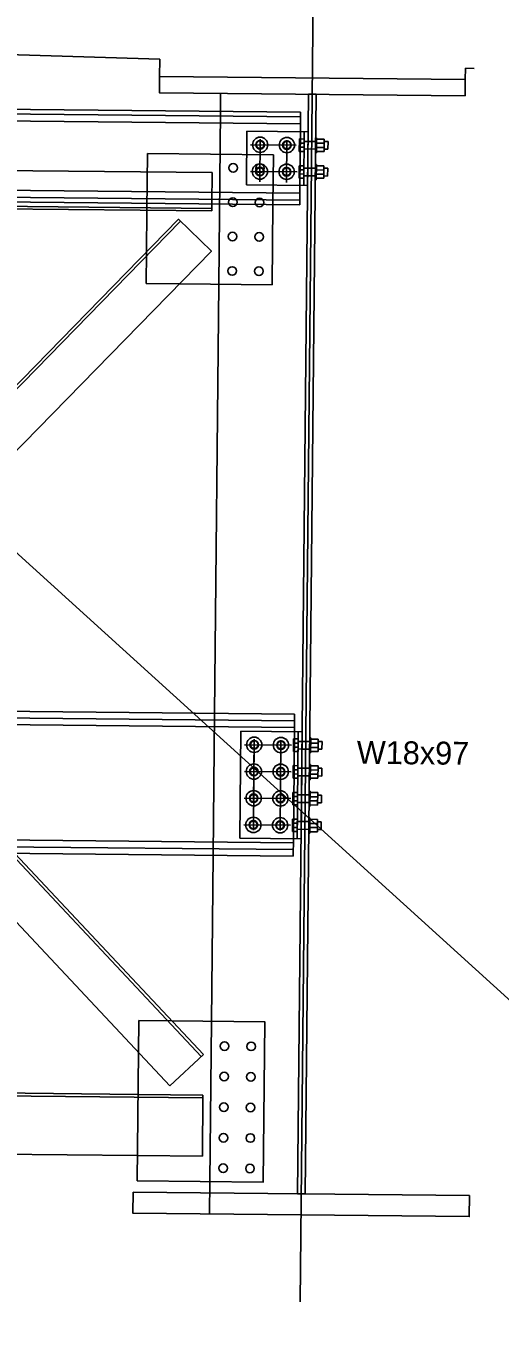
# Model space of a CAD drawing. Extents: x 632312 to 632885, y 378199 to 378534.
# Drawn here: x 632775.42 to 632780.59, y 378341.77 to 378355.92 of the extents above; entities that cross this region are included whole.
import ezdxf

# ---------------------------------------------------------------- set-up
doc = ezdxf.new("R2010")
doc.units = 0
for name, color, linetype in [('B_Boring', 7, 'Continuous'), ('B_Boring Annot', 7, 'Continuous'), ('R_Proposed Const Limits Cut', 7, 'Continuous'), ('R_Shade Removal', 7, 'Continuous'), ('R_Wall', 7, 'Continuous'), ('SHT_Dimensions', 7, 'Continuous'), ('USACE_Easement', 7, 'Continuous')]:
    doc.layers.add(name, color=color, linetype=linetype)

msp = doc.modelspace()

# ---------------------------------------------------------------- linework, layer by layer
at = {"layer": 'B_Boring'}
for p, q in [((632777.54, 378354.984), (632777.542, 378355.183)), ((632778.415, 378354.925), (632767.415, 378355.034)), ((632778.415, 378354.975), (632767.416, 378355.084)), ((632778.413, 378354.763), (632778.415, 378354.975)), ((632777.83, 378354.768), (632777.824, 378354.185)), ((632778.497, 378354.762), (632777.83, 378354.768)), ((632778.402, 378354.685), (632778.401, 378354.549)), ((632778.454, 378354.684), (632778.402, 378354.685)), ((632778.449, 378354.179), (632778.455, 378354.762)), ((632778.454, 378354.684), (632778.453, 378354.549)), ((632778.491, 378354.178), (632778.497, 378354.762)), ((632778.579, 378354.698), (632778.578, 378354.532)), ((632778.579, 378354.698), (632778.59, 378354.698)), ((632778.59, 378354.698), (632778.588, 378354.532)), ((632778.589, 378354.683), (632778.673, 378354.682)), ((632778.673, 378354.682), (632778.671, 378354.546)), ((632778.453, 378354.594), (632778.401, 378354.594)), ((632778.453, 378354.549), (632778.401, 378354.549)), ((632778.454, 378354.639), (632778.402, 378354.639)), ((632778.588, 378354.547), (632778.671, 378354.546)), ((632778.589, 378354.638), (632778.672, 378354.637)), ((632778.589, 378354.592), (632778.672, 378354.592)), ((632778.672, 378354.572), (632778.713, 378354.572)), ((632778.673, 378354.656), (632778.714, 378354.655)), ((632778.714, 378354.655), (632778.713, 378354.572)), ((632776.744, 378354.524), (632776.744, 378354.524)), ((632778.399, 378354.393), (632778.398, 378354.257)), ((632778.451, 378354.392), (632778.399, 378354.393)), ((632778.451, 378354.392), (632778.45, 378354.257)), ((632778.576, 378354.407), (632778.575, 378354.24)), ((632778.576, 378354.407), (632778.587, 378354.407)), ((632778.578, 378354.532), (632778.588, 378354.532)), ((632778.587, 378354.407), (632778.585, 378354.24)), ((632778.587, 378354.391), (632778.67, 378354.39)), ((632778.45, 378354.302), (632778.398, 378354.303)), ((632778.45, 378354.257), (632778.398, 378354.257)), ((632778.451, 378354.347), (632778.399, 378354.348)), ((632778.585, 378354.256), (632778.669, 378354.255)), ((632778.586, 378354.346), (632778.669, 378354.345)), ((632778.586, 378354.301), (632778.669, 378354.3)), ((632778.67, 378354.39), (632778.669, 378354.255)), ((632778.669, 378354.281), (632778.71, 378354.28)), ((632778.67, 378354.364), (632778.711, 378354.364)), ((632778.711, 378354.364), (632778.71, 378354.28)), ((632778.406, 378354.017), (632767.406, 378354.127)), ((632777.824, 378354.185), (632778.491, 378354.178)), ((632778.407, 378354.179), (632778.405, 378353.967)), ((632778.575, 378354.24), (632778.585, 378354.24)), ((632778.405, 378353.967), (632767.406, 378354.076)), ((632777.446, 378353.9), (632777.447, 378353.976)), ((632778.105, 378353.094), (632778.114, 378353.97)), ((632772.905, 378353.945), (632777.446, 378353.9)), ((632777.095, 378353.104), (632778.105, 378353.094)), ((632777.475, 378348.416), (632777.522, 378353.099)), ((632778.35, 378348.407), (632767.351, 378348.517)), ((632778.349, 378348.335), (632767.35, 378348.444)), ((632778.348, 378348.216), (632778.35, 378348.407)), ((632777.765, 378348.221), (632777.753, 378347.055)), ((632778.431, 378348.215), (632777.765, 378348.221)), ((632778.378, 378347.049), (632778.39, 378348.215)), ((632778.431, 378348.215), (632778.42, 378347.048)), ((632778.337, 378348.138), (632778.336, 378348.002)), ((632778.389, 378348.092), (632778.336, 378348.092)), ((632778.388, 378348.047), (632778.336, 378348.047)), ((632778.389, 378348.137), (632778.337, 378348.138)), ((632778.43, 378348.111), (632778.514, 378348.11)), ((632778.43, 378348.027), (632778.513, 378348.026)), ((632778.512, 378347.985), (632778.514, 378348.151)), ((632778.514, 378348.151), (632778.525, 378348.151)), ((632778.525, 378348.151), (632778.523, 378347.985)), ((632778.523, 378348.045), (632778.607, 378348.045)), ((632778.524, 378348.136), (632778.608, 378348.135)), ((632778.524, 378348.091), (632778.607, 378348.09)), ((632778.608, 378348.135), (632778.606, 378347.999)), ((632778.607, 378348.109), (632778.649, 378348.108)), ((632778.649, 378348.108), (632778.648, 378348.025)), ((632778.388, 378348.002), (632778.336, 378348.002)), ((632778.512, 378347.985), (632778.523, 378347.985)), ((632778.523, 378348), (632778.606, 378347.999)), ((632778.607, 378348.025), (632778.648, 378348.025)), ((632778.334, 378347.846), (632778.333, 378347.71)), ((632778.385, 378347.755), (632778.333, 378347.756)), ((632778.386, 378347.845), (632778.334, 378347.846)), ((632778.386, 378347.8), (632778.334, 378347.801)), ((632778.51, 378347.693), (632778.511, 378347.86)), ((632778.511, 378347.86), (632778.522, 378347.86)), ((632778.522, 378347.86), (632778.52, 378347.693)), ((632778.521, 378347.844), (632778.605, 378347.843)), ((632778.521, 378347.799), (632778.604, 378347.798)), ((632778.521, 378347.754), (632778.604, 378347.753)), ((632778.605, 378347.843), (632778.603, 378347.708)), ((632778.605, 378347.817), (632778.646, 378347.817)), ((632778.646, 378347.817), (632778.645, 378347.733)), ((632778.385, 378347.71), (632778.333, 378347.71)), ((632778.51, 378347.693), (632778.52, 378347.693)), ((632778.52, 378347.709), (632778.603, 378347.708)), ((632778.604, 378347.734), (632778.645, 378347.733)), ((632778.331, 378347.554), (632778.33, 378347.419)), ((632778.382, 378347.463), (632778.33, 378347.464)), ((632778.383, 378347.554), (632778.331, 378347.554)), ((632778.383, 378347.509), (632778.331, 378347.509)), ((632778.507, 378347.401), (632778.508, 378347.568)), ((632778.508, 378347.568), (632778.519, 378347.568)), ((632778.519, 378347.568), (632778.517, 378347.401)), ((632778.518, 378347.507), (632778.601, 378347.506)), ((632778.518, 378347.462), (632778.601, 378347.461)), ((632778.519, 378347.552), (632778.602, 378347.552)), ((632778.602, 378347.552), (632778.601, 378347.416)), ((632778.602, 378347.525), (632778.643, 378347.525)), ((632778.643, 378347.525), (632778.643, 378347.442)), ((632778.382, 378347.418), (632778.33, 378347.419)), ((632778.507, 378347.401), (632778.517, 378347.401)), ((632778.517, 378347.417), (632778.601, 378347.416)), ((632778.601, 378347.442), (632778.643, 378347.442)), ((632778.328, 378347.263), (632778.327, 378347.127)), ((632778.38, 378347.262), (632778.328, 378347.263)), ((632778.38, 378347.217), (632778.328, 378347.217)), ((632778.504, 378347.11), (632778.505, 378347.276)), ((632778.505, 378347.276), (632778.516, 378347.276)), ((632778.516, 378347.276), (632778.514, 378347.11)), ((632778.515, 378347.216), (632778.599, 378347.215)), ((632778.516, 378347.261), (632778.599, 378347.26)), ((632778.599, 378347.26), (632778.598, 378347.124)), ((632778.599, 378347.234), (632778.64, 378347.233)), ((632778.64, 378347.233), (632778.64, 378347.15)), ((632778.335, 378346.93), (632767.336, 378347.039)), ((632777.753, 378347.055), (632778.42, 378347.048)), ((632778.379, 378347.172), (632778.327, 378347.172)), ((632778.379, 378347.127), (632778.327, 378347.127)), ((632778.335, 378346.857), (632778.336, 378347.049)), ((632778.504, 378347.11), (632778.514, 378347.11)), ((632778.514, 378347.125), (632778.598, 378347.124)), ((632778.515, 378347.17), (632778.598, 378347.17)), ((632778.598, 378347.15), (632778.64, 378347.15)), ((632778.335, 378346.857), (632767.335, 378346.967)), ((632777.442, 378345.058), (632777.46, 378346.866)), ((632777.355, 378344.695), (632776.99, 378344.353)), ((632776.642, 378344.259), (632772.809, 378344.297)), ((632772.802, 378343.63), (632776.635, 378343.592)), ((632777.421, 378342.958), (632777.424, 378343.308))]:
    msp.add_line(p, q, dxfattribs=at)
for points in [[(632780.209, 378355.156), (632780.211, 378355.333), (632776.877, 378355.366), (632776.876, 378355.189)], [(632778.465, 378343.173), (632778.381, 378343.174), (632778.501, 378355.173), (632778.584, 378355.172)], [(632780.256, 378343.155), (632780.254, 378342.926), (632776.587, 378342.962), (632776.59, 378343.192)]]:
    msp.add_lwpolyline(points, close=True, dxfattribs=at)
for points in [[(632776.738, 378353.907), (632776.733, 378353.449)], [(632773.664, 378349.592), (632777.442, 378353.459), (632777.084, 378353.808), (632773.67, 378350.312)], [(632776.99, 378344.353), (632774.605, 378346.894)], [(632775.297, 378346.887), (632777.355, 378344.695)], [(632776.647, 378344.719), (632776.633, 378343.316), (632776.633, 378343.316), (632776.633, 378343.316), (632778.008, 378343.302), (632778.025, 378345.052), (632777.01, 378345.062)]]:
    msp.add_lwpolyline(points, dxfattribs=at)
for centre in [(632777.974, 378354.621), (632778.266, 378354.618), (632777.68, 378354.369), (632777.972, 378354.366), (632777.971, 378354.329), (632778.263, 378354.327), (632777.676, 378353.994), (632777.968, 378353.991), (632777.673, 378353.619), (632777.964, 378353.616), (632777.669, 378353.244), (632777.961, 378353.241), (632777.909, 378348.074), (632778.201, 378348.071), (632777.906, 378347.782), (632778.198, 378347.78), (632777.903, 378347.491), (632778.195, 378347.488), (632777.9, 378347.199), (632778.192, 378347.196), (632777.585, 378344.786), (632777.876, 378344.783), (632777.581, 378344.453), (632777.873, 378344.45), (632777.578, 378344.119), (632777.87, 378344.116), (632777.575, 378343.786), (632777.867, 378343.783), (632777.572, 378343.453), (632777.863, 378343.45)]:
    msp.add_circle(centre, 0.0469, dxfattribs=at)
at = {"layer": 'B_Boring Annot'}
for p, q in [((632772.922, 378355.674), (632776.879, 378355.556)), ((632776.879, 378355.556), (632776.877, 378355.366)), ((632780.211, 378355.333), (632780.212, 378355.456)), ((632780.212, 378355.456), (632780.308, 378355.453)), ((632776.877, 378355.366), (632780.211, 378355.333))]:
    msp.add_line(p, q, dxfattribs=at)
at = {"layer": 'R_Proposed Const Limits Cut'}
for p, q in [((632778.414, 378354.85), (632767.415, 378354.959)), ((632777.522, 378353.099), (632777.54, 378354.984)), ((632778.407, 378354.179), (632778.413, 378354.763)), ((632778.453, 378354.575), (632778.578, 378354.573)), ((632778.454, 378354.658), (632778.579, 378354.657)), ((632777.45, 378354.317), (632768.367, 378354.407)), ((632776.738, 378353.907), (632776.744, 378354.524)), ((632778.119, 378354.51), (632776.744, 378354.524)), ((632778.119, 378354.51), (632778.114, 378353.97)), ((632777.447, 378353.976), (632777.45, 378354.317)), ((632778.45, 378354.283), (632778.575, 378354.282)), ((632778.451, 378354.366), (632778.576, 378354.365)), ((632778.407, 378354.092), (632767.407, 378354.201)), ((632777.447, 378353.926), (632768.364, 378354.017)), ((632768.701, 378353.87), (632777.332, 378344.674)), ((632777.107, 378353.787), (632768.294, 378344.764)), ((632776.733, 378353.449), (632776.73, 378353.107)), ((632777.095, 378353.104), (632776.73, 378353.107)), ((632778.349, 378348.261), (632767.349, 378348.371)), ((632777.475, 378348.416), (632777.46, 378346.866)), ((632778.348, 378348.216), (632778.336, 378347.049)), ((632778.388, 378348.028), (632778.43, 378348.027)), ((632778.389, 378348.111), (632778.43, 378348.111)), ((632778.386, 378347.819), (632778.511, 378347.818)), ((632778.385, 378347.736), (632778.51, 378347.735)), ((632778.383, 378347.528), (632778.508, 378347.526)), ((632778.382, 378347.444), (632778.507, 378347.443)), ((632778.38, 378347.236), (632778.505, 378347.235)), ((632778.336, 378347.003), (632767.337, 378347.112)), ((632778.379, 378347.153), (632778.504, 378347.151)), ((632776.647, 378344.719), (632776.65, 378345.066)), ((632777.01, 378345.062), (632776.65, 378345.066)), ((632777.442, 378345.058), (632777.424, 378343.308)), ((632777.35, 378344.22), (632768.267, 378344.311)), ((632777.35, 378344.252), (632776.642, 378344.259)), ((632777.344, 378343.585), (632777.35, 378344.252)), ((632776.635, 378343.592), (632777.344, 378343.585))]:
    msp.add_line(p, q, dxfattribs=at)
for centre, radius in [((632777.974, 378354.621), 0.0833), ((632778.266, 378354.618), 0.0833), ((632777.974, 378354.621), 0.0417), ((632778.266, 378354.618), 0.0417), ((632777.971, 378354.329), 0.0833), ((632778.263, 378354.327), 0.0833), ((632777.971, 378354.329), 0.0417), ((632778.263, 378354.327), 0.0417), ((632777.909, 378348.074), 0.0833), ((632777.909, 378348.074), 0.0417), ((632778.201, 378348.071), 0.0833), ((632778.201, 378348.071), 0.0417), ((632777.906, 378347.782), 0.0833), ((632777.906, 378347.782), 0.0417), ((632778.198, 378347.78), 0.0833), ((632778.198, 378347.78), 0.0417), ((632777.903, 378347.491), 0.0833), ((632777.903, 378347.491), 0.0417), ((632778.195, 378347.488), 0.0833), ((632778.195, 378347.488), 0.0417), ((632777.9, 378347.199), 0.0833), ((632777.9, 378347.199), 0.0417), ((632778.192, 378347.196), 0.0833), ((632778.192, 378347.196), 0.0417)]:
    msp.add_circle(centre, radius, dxfattribs=at)
at = {"layer": 'R_Shade Removal'}
msp.add_line((632778.411, 378341.996), (632778.561, 378357.061), dxfattribs=at)
at = {"layer": 'R_Wall'}
for p, q in [((632777.975, 378354.682), (632777.97, 378354.217)), ((632777.87, 378354.622), (632778.365, 378354.617)), ((632778.266, 378354.672), (632778.262, 378354.209)), ((632777.867, 378354.33), (632778.377, 378354.325)), ((632777.805, 378348.075), (632778.315, 378348.07)), ((632777.91, 378348.135), (632777.9, 378347.141)), ((632778.201, 378348.125), (632778.192, 378347.14)), ((632777.802, 378347.783), (632778.312, 378347.778)), ((632777.799, 378347.492), (632778.309, 378347.487)), ((632777.796, 378347.2), (632778.306, 378347.195))]:
    msp.add_line(p, q, dxfattribs=at)
at = {"layer": 'SHT_Dimensions'}
for p, q in [((632777.91, 378348.135), (632777.903, 378347.444)), ((632778.389, 378348.137), (632778.388, 378348.002)), ((632778.386, 378347.845), (632778.385, 378347.71)), ((632778.383, 378347.554), (632778.382, 378347.418)), ((632778.38, 378347.262), (632778.379, 378347.127))]:
    msp.add_line(p, q, dxfattribs=at)
at = {"layer": 'USACE_Easement'}
msp.add_line((632763.709, 378360.709), (632793.415, 378333.735), dxfattribs=at)

# ---------------------------------------------------------------- texts
at = {"layer": 'SHT_Dimensions'}
msp.add_text('W18x97', height=0.25, rotation=359.4304, dxfattribs=at).set_placement((632779.027, 378347.867))

doc.saveas('drawing.dxf')
